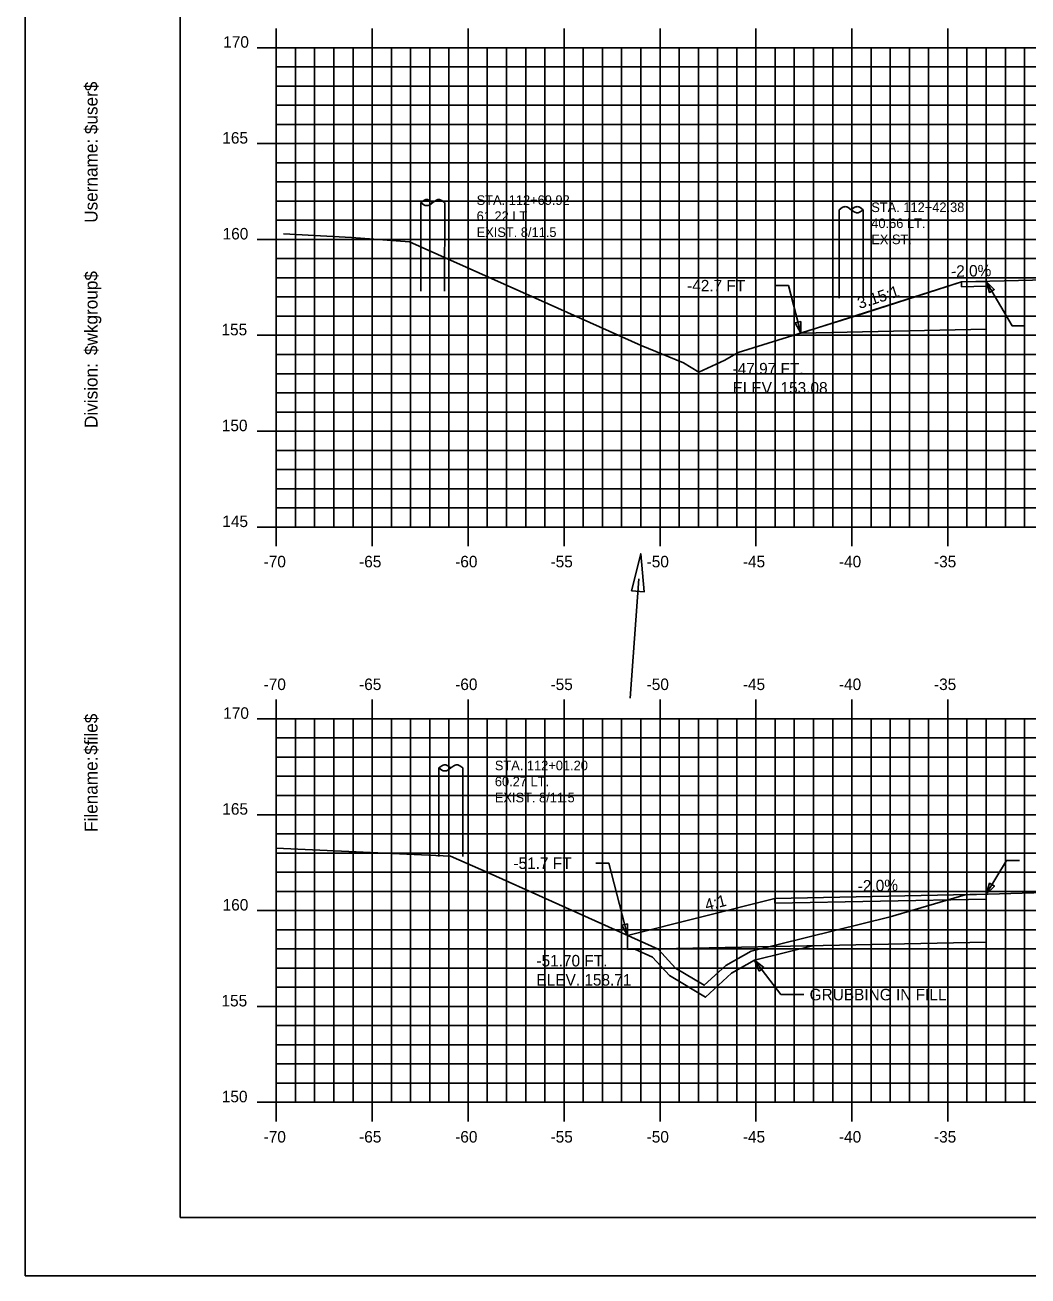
# Model space of a CAD drawing. Extents: x 1668694 to 1668864, y 337823 to 337933.
# Drawn here: x 1668694.4 to 1668746.7, y 337823.4 to 337888.6 of the extents above; entities that cross this region are included whole.
import ezdxf

# ---------------------------------------------------------------- set-up
doc = ezdxf.new("R2010")
doc.units = 0
for name, color, linetype in [('ANNOTATION', 7, 'Continuous'), ('BORDER', 7, 'Continuous'), ('D_Drainage_Ditch_Line', 7, 'Continuous'), ('D_Roadway_Pavement', 7, 'Continuous'), ('D_Text_Monospaced', 7, 'Continuous'), ('D_Text_Standard', 7, 'Continuous'), ('Grubbing in Fill', 7, 'Continuous'), ('H_V ANNOTATION', 7, 'Continuous'), ('MAJOR', 7, 'Continuous'), ('MINOR', 7, 'Continuous'), ('PLOT BOUNDARY', 7, 'Continuous'), ('S_Roadway_Centerline', 7, 'Continuous'), ('S_Utilities_Pole_Joint', 7, 'Continuous')]:
    doc.layers.add(name, color=color, linetype=linetype)

msp = doc.modelspace()

# ---------------------------------------------------------------- linework, layer by layer
at = {"layer": 'ANNOTATION'}
for p, q in [((1668734.884, 337872.572), (1668743.261, 337875.234)), ((1668733.532, 337842.833), (1668733.532, 337843.083)), ((1668725.843, 337841.16), (1668725.843, 337840.429)), ((1668732.472, 337839.863), (1668733.839, 337838.07)), ((1668735.039, 337838.07), (1668733.839, 337838.07))]:
    msp.add_line(p, q, dxfattribs=at)
msp.add_lwpolyline([(1668732.716, 337839.295), (1668732.472, 337839.863), (1668732.955, 337839.477)], close=True, dxfattribs=at)
at = {"layer": 'BORDER'}
for p, q in [((1668702.542, 337931.453), (1668702.542, 337826.453)), ((1668702.542, 337826.453), (1668862.542, 337826.453))]:
    msp.add_line(p, q, dxfattribs=at)
at = {"layer": 'D_Drainage_Ditch_Line'}
msp.add_line((1668726.44, 337859.756), (1668725.984, 337853.529), dxfattribs=at)
msp.add_lwpolyline([(1668726.065, 337859.125), (1668726.719, 337859.077), (1668726.535, 337861.064)], close=True, dxfattribs=at)
at = {"layer": 'D_Roadway_Pavement'}
for p, q in [((1668744.542, 337875.266), (1668743.261, 337875.24)), ((1668743.261, 337874.99), (1668743.261, 337875.24)), ((1668744.542, 337875.016), (1668743.261, 337874.99)), ((1668744.542, 337875.266), (1668744.542, 337875.016)), ((1668744.542, 337875.266), (1668744.542, 337872.766)), ((1668744.542, 337872.766), (1668734.884, 337872.572)), ((1668733.532, 337843.083), (1668725.843, 337841.16)), ((1668744.542, 337843.303), (1668733.532, 337843.083)), ((1668744.542, 337843.053), (1668733.532, 337842.833)), ((1668744.542, 337843.303), (1668744.542, 337840.803)), ((1668744.542, 337840.803), (1668725.843, 337840.429))]:
    msp.add_line(p, q, dxfattribs=at)
at = {"layer": 'D_Text_Standard'}
for points in [[(1668734.884, 337872.572), (1668734.231, 337875.043), (1668733.551, 337875.043)], [(1668744.542, 337875.266), (1668745.893, 337872.953), (1668746.573, 337872.953)], [(1668744.542, 337843.303), (1668745.602, 337845.059), (1668746.281, 337845.059)], [(1668725.843, 337841.16), (1668724.88, 337844.923), (1668724.2, 337844.923)]]:
    msp.add_lwpolyline(points, dxfattribs=at)
for points in [[(1668744.542, 337875.266), (1668744.961, 337874.836), (1668744.71, 337874.69)], [(1668734.884, 337872.572), (1668734.595, 337873.098), (1668734.876, 337873.172)], [(1668744.542, 337843.303), (1668744.718, 337843.877), (1668744.967, 337843.726)], [(1668725.843, 337841.16), (1668725.558, 337841.688), (1668725.84, 337841.76)]]:
    msp.add_lwpolyline(points, close=True, dxfattribs=at)
at = {"layer": 'Grubbing in Fill'}
msp.add_line((1668725.843, 337841.16), (1668725.843, 337840.612), dxfattribs=at)
msp.add_lwpolyline([(1668726.232, 337840.437), (1668727.153, 337840.022), (1668728.032, 337839.061), (1668729.912, 337837.932), (1668731.263, 337839.184), (1668732.472, 337839.863), (1668735.56, 337840.623)], dxfattribs=at)
at = {"layer": 'MAJOR'}
for p, q in [((1668707.542, 337888.455), (1668707.542, 337887.453)), ((1668712.542, 337888.455), (1668712.542, 337887.453)), ((1668717.542, 337888.455), (1668717.542, 337887.453)), ((1668722.542, 337888.455), (1668722.542, 337887.453)), ((1668727.542, 337888.455), (1668727.542, 337887.453)), ((1668732.542, 337888.455), (1668732.542, 337887.453)), ((1668737.542, 337888.455), (1668737.542, 337887.453)), ((1668742.542, 337888.455), (1668742.542, 337887.453)), ((1668706.54, 337887.453), (1668707.542, 337887.453)), ((1668707.542, 337887.453), (1668847.542, 337887.453)), ((1668707.542, 337862.453), (1668707.542, 337887.453)), ((1668707.542, 337862.453), (1668707.542, 337887.453)), ((1668707.542, 337887.453), (1668847.542, 337887.453)), ((1668712.542, 337862.453), (1668712.542, 337887.453)), ((1668717.542, 337862.453), (1668717.542, 337887.453)), ((1668722.542, 337862.453), (1668722.542, 337887.453)), ((1668727.542, 337862.453), (1668727.542, 337887.453)), ((1668732.542, 337862.453), (1668732.542, 337887.453)), ((1668737.542, 337862.453), (1668737.542, 337887.453)), ((1668742.542, 337862.453), (1668742.542, 337887.453)), ((1668706.54, 337882.453), (1668707.542, 337882.453)), ((1668707.542, 337882.453), (1668847.542, 337882.453)), ((1668706.54, 337877.453), (1668707.542, 337877.453)), ((1668707.542, 337877.453), (1668847.542, 337877.453)), ((1668706.54, 337872.453), (1668707.542, 337872.453)), ((1668707.542, 337872.453), (1668847.542, 337872.453)), ((1668706.54, 337867.453), (1668707.542, 337867.453)), ((1668707.542, 337867.453), (1668847.542, 337867.453)), ((1668706.54, 337862.453), (1668707.542, 337862.453)), ((1668707.542, 337862.453), (1668847.542, 337862.453)), ((1668707.542, 337862.453), (1668847.542, 337862.453)), ((1668707.542, 337861.451), (1668707.542, 337862.453)), ((1668712.542, 337861.451), (1668712.542, 337862.453)), ((1668717.542, 337861.451), (1668717.542, 337862.453)), ((1668722.542, 337861.451), (1668722.542, 337862.453)), ((1668727.542, 337861.451), (1668727.542, 337862.453)), ((1668732.542, 337861.451), (1668732.542, 337862.453)), ((1668737.542, 337861.451), (1668737.542, 337862.453)), ((1668742.542, 337861.451), (1668742.542, 337862.453)), ((1668707.542, 337853.455), (1668707.542, 337852.453)), ((1668712.542, 337853.455), (1668712.542, 337852.453)), ((1668717.542, 337853.455), (1668717.542, 337852.453)), ((1668722.542, 337853.455), (1668722.542, 337852.453)), ((1668727.542, 337853.455), (1668727.542, 337852.453)), ((1668732.542, 337853.455), (1668732.542, 337852.453)), ((1668737.542, 337853.455), (1668737.542, 337852.453)), ((1668742.542, 337853.455), (1668742.542, 337852.453)), ((1668706.54, 337852.453), (1668707.542, 337852.453)), ((1668707.542, 337852.453), (1668847.542, 337852.453)), ((1668707.542, 337832.453), (1668707.542, 337852.453)), ((1668707.542, 337832.453), (1668707.542, 337852.453)), ((1668707.542, 337852.453), (1668847.542, 337852.453)), ((1668712.542, 337832.453), (1668712.542, 337852.453)), ((1668717.542, 337832.453), (1668717.542, 337852.453)), ((1668722.542, 337832.453), (1668722.542, 337852.453)), ((1668727.542, 337832.453), (1668727.542, 337852.453)), ((1668732.542, 337832.453), (1668732.542, 337852.453)), ((1668737.542, 337832.453), (1668737.542, 337852.453)), ((1668742.542, 337832.453), (1668742.542, 337852.453)), ((1668706.54, 337847.453), (1668707.542, 337847.453)), ((1668707.542, 337847.453), (1668847.542, 337847.453)), ((1668706.54, 337842.453), (1668707.542, 337842.453)), ((1668707.542, 337842.453), (1668847.542, 337842.453)), ((1668706.54, 337837.453), (1668707.542, 337837.453)), ((1668707.542, 337837.453), (1668847.542, 337837.453)), ((1668706.54, 337832.453), (1668707.542, 337832.453)), ((1668707.542, 337832.453), (1668847.542, 337832.453)), ((1668707.542, 337832.453), (1668847.542, 337832.453)), ((1668707.542, 337831.451), (1668707.542, 337832.453)), ((1668712.542, 337831.451), (1668712.542, 337832.453)), ((1668717.542, 337831.451), (1668717.542, 337832.453)), ((1668722.542, 337831.451), (1668722.542, 337832.453)), ((1668727.542, 337831.451), (1668727.542, 337832.453)), ((1668732.542, 337831.451), (1668732.542, 337832.453)), ((1668737.542, 337831.451), (1668737.542, 337832.453)), ((1668742.542, 337831.451), (1668742.542, 337832.453))]:
    msp.add_line(p, q, dxfattribs=at)
at = {"layer": 'MINOR'}
for p, q in [((1668708.542, 337862.453), (1668708.542, 337887.453)), ((1668709.542, 337862.453), (1668709.542, 337887.453)), ((1668710.542, 337862.453), (1668710.542, 337887.453)), ((1668711.542, 337862.453), (1668711.542, 337887.453)), ((1668713.542, 337862.453), (1668713.542, 337887.453)), ((1668714.542, 337862.453), (1668714.542, 337887.453)), ((1668715.542, 337862.453), (1668715.542, 337887.453)), ((1668716.542, 337862.453), (1668716.542, 337887.453)), ((1668718.542, 337862.453), (1668718.542, 337887.453)), ((1668719.542, 337862.453), (1668719.542, 337887.453)), ((1668720.542, 337862.453), (1668720.542, 337887.453)), ((1668721.542, 337862.453), (1668721.542, 337887.453)), ((1668723.542, 337862.453), (1668723.542, 337887.453)), ((1668724.542, 337862.453), (1668724.542, 337887.453)), ((1668725.542, 337862.453), (1668725.542, 337887.453)), ((1668726.542, 337862.453), (1668726.542, 337887.453)), ((1668728.542, 337862.453), (1668728.542, 337887.453)), ((1668729.542, 337862.453), (1668729.542, 337887.453)), ((1668730.542, 337862.453), (1668730.542, 337887.453)), ((1668731.542, 337862.453), (1668731.542, 337887.453)), ((1668733.542, 337862.453), (1668733.542, 337887.453)), ((1668734.542, 337862.453), (1668734.542, 337887.453)), ((1668735.542, 337862.453), (1668735.542, 337887.453)), ((1668736.542, 337862.453), (1668736.542, 337887.453)), ((1668738.542, 337862.453), (1668738.542, 337887.453)), ((1668739.542, 337862.453), (1668739.542, 337887.453)), ((1668740.542, 337862.453), (1668740.542, 337887.453)), ((1668741.542, 337862.453), (1668741.542, 337887.453)), ((1668743.542, 337862.453), (1668743.542, 337887.453)), ((1668744.542, 337862.453), (1668744.542, 337887.453)), ((1668745.542, 337862.453), (1668745.542, 337887.453)), ((1668746.542, 337862.453), (1668746.542, 337887.453)), ((1668707.542, 337886.453), (1668847.542, 337886.453)), ((1668707.542, 337886.453), (1668708.544, 337886.453)), ((1668707.542, 337885.453), (1668847.542, 337885.453)), ((1668707.542, 337885.453), (1668708.544, 337885.453)), ((1668707.542, 337884.453), (1668847.542, 337884.453)), ((1668707.542, 337884.453), (1668708.544, 337884.453)), ((1668707.542, 337883.453), (1668847.542, 337883.453)), ((1668707.542, 337883.453), (1668708.544, 337883.453)), ((1668707.542, 337881.453), (1668847.542, 337881.453)), ((1668707.542, 337881.453), (1668708.544, 337881.453)), ((1668707.542, 337880.453), (1668847.542, 337880.453)), ((1668707.542, 337880.453), (1668708.544, 337880.453)), ((1668707.542, 337879.453), (1668847.542, 337879.453)), ((1668707.542, 337879.453), (1668708.544, 337879.453)), ((1668707.542, 337878.453), (1668847.542, 337878.453)), ((1668707.542, 337878.453), (1668708.544, 337878.453)), ((1668707.542, 337876.453), (1668847.542, 337876.453)), ((1668707.542, 337876.453), (1668708.544, 337876.453)), ((1668707.542, 337875.453), (1668847.542, 337875.453)), ((1668707.542, 337875.453), (1668708.544, 337875.453)), ((1668707.542, 337874.453), (1668847.542, 337874.453)), ((1668707.542, 337874.453), (1668708.544, 337874.453)), ((1668707.542, 337873.453), (1668847.542, 337873.453)), ((1668707.542, 337873.453), (1668708.544, 337873.453)), ((1668707.542, 337871.453), (1668847.542, 337871.453)), ((1668707.542, 337871.453), (1668708.544, 337871.453)), ((1668707.542, 337870.453), (1668847.542, 337870.453)), ((1668707.542, 337870.453), (1668708.544, 337870.453)), ((1668707.542, 337869.453), (1668847.542, 337869.453)), ((1668707.542, 337869.453), (1668708.544, 337869.453)), ((1668707.542, 337868.453), (1668847.542, 337868.453)), ((1668707.542, 337868.453), (1668708.544, 337868.453)), ((1668707.542, 337866.453), (1668847.542, 337866.453)), ((1668707.542, 337866.453), (1668708.544, 337866.453)), ((1668707.542, 337865.453), (1668847.542, 337865.453)), ((1668707.542, 337865.453), (1668708.544, 337865.453)), ((1668707.542, 337864.453), (1668847.542, 337864.453)), ((1668707.542, 337864.453), (1668708.544, 337864.453)), ((1668707.542, 337863.453), (1668847.542, 337863.453)), ((1668707.542, 337863.453), (1668708.544, 337863.453)), ((1668708.542, 337832.453), (1668708.542, 337852.453)), ((1668709.542, 337832.453), (1668709.542, 337852.453)), ((1668710.542, 337832.453), (1668710.542, 337852.453)), ((1668711.542, 337832.453), (1668711.542, 337852.453)), ((1668713.542, 337832.453), (1668713.542, 337852.453)), ((1668714.542, 337832.453), (1668714.542, 337852.453)), ((1668715.542, 337832.453), (1668715.542, 337852.453)), ((1668716.542, 337832.453), (1668716.542, 337852.453)), ((1668718.542, 337832.453), (1668718.542, 337852.453)), ((1668719.542, 337832.453), (1668719.542, 337852.453)), ((1668720.542, 337832.453), (1668720.542, 337852.453)), ((1668721.542, 337832.453), (1668721.542, 337852.453)), ((1668723.542, 337832.453), (1668723.542, 337852.453)), ((1668724.542, 337832.453), (1668724.542, 337852.453)), ((1668725.542, 337832.453), (1668725.542, 337852.453)), ((1668726.542, 337832.453), (1668726.542, 337852.453)), ((1668728.542, 337832.453), (1668728.542, 337852.453)), ((1668729.542, 337832.453), (1668729.542, 337852.453)), ((1668730.542, 337832.453), (1668730.542, 337852.453)), ((1668731.542, 337832.453), (1668731.542, 337852.453)), ((1668733.542, 337832.453), (1668733.542, 337852.453)), ((1668734.542, 337832.453), (1668734.542, 337852.453)), ((1668735.542, 337832.453), (1668735.542, 337852.453)), ((1668736.542, 337832.453), (1668736.542, 337852.453)), ((1668738.542, 337832.453), (1668738.542, 337852.453)), ((1668739.542, 337832.453), (1668739.542, 337852.453)), ((1668740.542, 337832.453), (1668740.542, 337852.453)), ((1668741.542, 337832.453), (1668741.542, 337852.453)), ((1668743.542, 337832.453), (1668743.542, 337852.453)), ((1668744.542, 337832.453), (1668744.542, 337852.453)), ((1668745.542, 337832.453), (1668745.542, 337852.453)), ((1668746.542, 337832.453), (1668746.542, 337852.453)), ((1668707.542, 337851.453), (1668847.542, 337851.453)), ((1668707.542, 337851.453), (1668708.544, 337851.453)), ((1668707.542, 337850.453), (1668847.542, 337850.453)), ((1668707.542, 337850.453), (1668708.544, 337850.453)), ((1668707.542, 337849.453), (1668847.542, 337849.453)), ((1668707.542, 337849.453), (1668708.544, 337849.453)), ((1668707.542, 337848.453), (1668847.542, 337848.453)), ((1668707.542, 337848.453), (1668708.544, 337848.453)), ((1668707.542, 337846.453), (1668847.542, 337846.453)), ((1668707.542, 337846.453), (1668708.544, 337846.453)), ((1668707.542, 337845.453), (1668847.542, 337845.453)), ((1668707.542, 337845.453), (1668708.544, 337845.453)), ((1668707.542, 337844.453), (1668847.542, 337844.453)), ((1668707.542, 337844.453), (1668708.544, 337844.453)), ((1668707.542, 337843.453), (1668847.542, 337843.453)), ((1668707.542, 337843.453), (1668708.544, 337843.453)), ((1668707.542, 337841.453), (1668847.542, 337841.453)), ((1668707.542, 337841.453), (1668708.544, 337841.453)), ((1668707.542, 337840.453), (1668847.542, 337840.453)), ((1668707.542, 337840.453), (1668708.544, 337840.453)), ((1668707.542, 337839.453), (1668847.542, 337839.453)), ((1668707.542, 337839.453), (1668708.544, 337839.453)), ((1668707.542, 337838.453), (1668847.542, 337838.453)), ((1668707.542, 337838.453), (1668708.544, 337838.453)), ((1668707.542, 337836.453), (1668847.542, 337836.453)), ((1668707.542, 337836.453), (1668708.544, 337836.453)), ((1668707.542, 337835.453), (1668847.542, 337835.453)), ((1668707.542, 337835.453), (1668708.544, 337835.453)), ((1668707.542, 337834.453), (1668847.542, 337834.453)), ((1668707.542, 337834.453), (1668708.544, 337834.453)), ((1668707.542, 337833.453), (1668847.542, 337833.453)), ((1668707.542, 337833.453), (1668708.544, 337833.453))]:
    msp.add_line(p, q, dxfattribs=at)
at = {"layer": 'PLOT BOUNDARY'}
msp.add_lwpolyline([(1668694.449, 337823.394), (1668864.449, 337823.394), (1668864.449, 337933.394), (1668694.449, 337933.394)], close=True, dxfattribs=at)
at = {"layer": 'S_Roadway_Centerline'}
for points in [[(1668707.926, 337877.74), (1668711.458, 337877.552), (1668714.49, 337877.328), (1668721.715, 337874.101), (1668726.556, 337871.915), (1668728.76, 337871.024), (1668729.57, 337870.535), (1668730.921, 337871.165), (1668731.618, 337871.557), (1668737.822, 337873.486), (1668742.511, 337874.996), (1668743.261, 337875.234), (1668754.371, 337875.508), (1668754.902, 337875.52), (1668755.227, 337875.5), (1668767.145, 337874.83), (1668773.992, 337874.351), (1668780.417, 337873.876), (1668780.926, 337874.122), (1668781.008, 337874.174)], [(1668707.542, 337845.711), (1668716.631, 337845.281), (1668718.644, 337844.402), (1668727.452, 337840.436), (1668728.352, 337839.452), (1668729.848, 337838.554), (1668730.966, 337839.591), (1668732.286, 337840.332), (1668739.534, 337842.117), (1668743.45, 337843.271), (1668747.609, 337843.393), (1668754.663, 337843.611), (1668760.806, 337843.271), (1668767.412, 337842.94), (1668776.054, 337842.121), (1668779.365, 337841.912), (1668780.501, 337842.004), (1668780.972, 337842.193), (1668781.252, 337842.292)]]:
    msp.add_lwpolyline(points, dxfattribs=at)
at = {"layer": 'S_Utilities_Pole_Joint'}
for p, q in [((1668715.069, 337879.376), (1668715.226, 337879.487)), ((1668715.069, 337874.757), (1668715.073, 337879.376)), ((1668715.226, 337879.265), (1668715.069, 337879.376)), ((1668715.538, 337879.487), (1668715.695, 337879.376)), ((1668715.695, 337879.376), (1668715.538, 337879.265)), ((1668715.851, 337879.487), (1668715.695, 337879.376)), ((1668716.319, 337879.376), (1668716.163, 337879.487)), ((1668716.319, 337874.757), (1668716.323, 337879.376)), ((1668736.886, 337874.383), (1668736.883, 337879.003)), ((1668736.886, 337879.003), (1668737.042, 337879.113)), ((1668737.354, 337879.113), (1668737.511, 337879.003)), ((1668737.667, 337879.113), (1668737.511, 337879.003)), ((1668737.511, 337879.003), (1668737.667, 337878.892)), ((1668738.136, 337879.003), (1668737.98, 337879.113)), ((1668737.98, 337878.892), (1668738.136, 337879.003)), ((1668738.136, 337874.383), (1668738.133, 337879.003)), ((1668716.018, 337849.892), (1668716.174, 337850.002)), ((1668716.018, 337845.272), (1668716.021, 337849.892)), ((1668716.174, 337849.781), (1668716.018, 337849.892)), ((1668716.486, 337850.002), (1668716.643, 337849.892)), ((1668716.643, 337849.892), (1668716.486, 337849.781)), ((1668716.799, 337850.002), (1668716.643, 337849.892)), ((1668717.268, 337849.892), (1668717.111, 337850.002)), ((1668717.268, 337845.272), (1668717.271, 337849.892))]:
    msp.add_line(p, q, dxfattribs=at)
for centre, start, end in [((1668715.382, 337879.266), 90, 125.26439), ((1668715.382, 337879.266), 54.73561, 90), ((1668716.007, 337879.266), 90, 125.26439), ((1668716.007, 337879.266), 54.73561, 90), ((1668715.382, 337879.487), 234.73561, 270), ((1668715.382, 337879.487), 270, 305.26439), ((1668737.198, 337878.892), 90, 125.26439), ((1668737.198, 337878.892), 54.73561, 90), ((1668737.823, 337878.892), 90, 125.26439), ((1668737.823, 337879.113), 234.73561, 270), ((1668737.823, 337878.892), 54.73561, 90), ((1668737.823, 337879.113), 270, 305.26439), ((1668716.33, 337849.781), 90, 125.26439), ((1668716.33, 337850.002), 234.73561, 270), ((1668716.33, 337849.781), 54.73561, 90), ((1668716.33, 337850.002), 270, 305.26439), ((1668716.955, 337849.781), 90, 125.26439), ((1668716.955, 337849.781), 54.73561, 90)]:
    msp.add_arc(centre, 0.271, start, end, dxfattribs=at)

# ---------------------------------------------------------------- texts
at = {"layer": 'ANNOTATION'}
for s, rotation, p in [('-2.0%', 1.14576, (1668742.719, 337875.496)), ('3.15:1', 17.62755, (1668737.94, 337873.823)), ('-2.0%', 1.14576, (1668737.855, 337843.436)), ('4:1', 14.03624, (1668729.964, 337842.441))]:
    msp.add_text(s, height=0.6, rotation=rotation, dxfattribs=at).set_placement(p)
msp.add_text('GRUBBING IN FILL ', height=0.6, dxfattribs=at).set_placement((1668735.339, 337837.77))
at = {"layer": 'BORDER'}
for s, p in [('$user$', (1668698.227, 337882.945)), ('Username:', (1668698.227, 337878.321)), ('$wkgroup$', (1668698.227, 337871.423)), ('Division:', (1668698.227, 337867.62)), ('$file$', (1668698.227, 337850.579)), ('Filename:', (1668698.227, 337846.552))]:
    msp.add_text(s, height=0.6696, rotation=90, dxfattribs=at).set_placement(p)
at = {"layer": 'D_Text_Monospaced'}
for s, height, p in [('STA. 112+69.92', 0.49998, (1668717.986, 337879.255)), ('61.22 LT.', 0.5, (1668717.986, 337878.421)), ('STA. 112+42.38', 0.49998, (1668738.553, 337878.881)), ('40.66 LT.', 0.5, (1668738.553, 337878.047)), ('EXIST. 8/11.5', 0.49998, (1668717.986, 337877.581)), ('EXIST. ', 0.5, (1668738.553, 337877.207)), ('STA. 112+01.20', 0.49998, (1668718.934, 337849.77)), ('60.27 LT.', 0.5, (1668718.934, 337848.936)), ('EXIST. 8/11.5', 0.49998, (1668718.934, 337848.096))]:
    msp.add_text(s, height=height, dxfattribs=at).set_placement(p)
at = {"layer": 'D_Text_Standard'}
for s, p in [('-42.7 FT', (1668728.952, 337874.743)), ('-47.97 FT.', (1668731.325, 337870.414)), ('ELEV. 153.08', (1668731.325, 337869.414)), ('-51.7 FT', (1668719.901, 337844.623)), ('-51.70 FT.', (1668721.102, 337839.538)), ('ELEV. 158.71', (1668721.102, 337838.538))]:
    msp.add_text(s, height=0.6, dxfattribs=at).set_placement(p)
at = {"layer": 'H_V ANNOTATION'}
for s, p in [('170', (1668704.779, 337887.453)), ('165', (1668704.731, 337882.453)), ('160', (1668704.747, 337877.453)), ('155', (1668704.688, 337872.453)), ('150', (1668704.704, 337867.453)), ('145', (1668704.731, 337862.453)), ('-70', (1668706.884, 337860.353)), ('-65', (1668711.86, 337860.353)), ('-60', (1668716.868, 337860.353)), ('-55', (1668721.838, 337860.353)), ('-50', (1668726.846, 337860.353)), ('-45', (1668731.86, 337860.353)), ('-40', (1668736.868, 337860.353)), ('-35', (1668741.822, 337860.353)), ('-70', (1668706.884, 337853.953)), ('-65', (1668711.86, 337853.953)), ('-60', (1668716.868, 337853.953)), ('-55', (1668721.838, 337853.953)), ('-50', (1668726.846, 337853.953)), ('-45', (1668731.86, 337853.953)), ('-40', (1668736.868, 337853.953)), ('-35', (1668741.822, 337853.953)), ('170', (1668704.779, 337852.453)), ('165', (1668704.731, 337847.453)), ('160', (1668704.747, 337842.453)), ('155', (1668704.688, 337837.453)), ('150', (1668704.704, 337832.453)), ('-70', (1668706.884, 337830.353)), ('-65', (1668711.86, 337830.353)), ('-60', (1668716.868, 337830.353)), ('-55', (1668721.838, 337830.353)), ('-50', (1668726.846, 337830.353)), ('-45', (1668731.86, 337830.353)), ('-40', (1668736.868, 337830.353)), ('-35', (1668741.822, 337830.353))]:
    msp.add_text(s, height=0.6, dxfattribs=at).set_placement(p)
at = {"layer": 'MAJOR'}
for p in [(1668707.538, 337862.453), (1668707.538, 337832.453)]:
    msp.add_text('-', height=0.006, dxfattribs=at).set_placement(p)

doc.saveas('drawing.dxf')
